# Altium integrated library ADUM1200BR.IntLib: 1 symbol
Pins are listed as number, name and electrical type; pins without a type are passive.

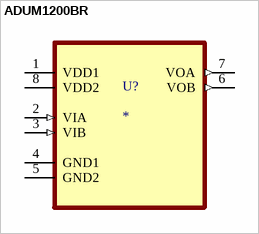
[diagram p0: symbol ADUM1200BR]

## ADUM1200BR
designator U?
General Purpose Digital Isolator 2500Vrms 2 Channel 10Mbps 25kV/Âµs CMTI 8-SOIC (0.154, 3.90mm Width); MF: Analog Devices; MP: ADUM1200BR
footprint SOIC127P600X175-8N
pins: 1 VDD1 (power), 2 VIA (in), 3 VIB (in), 4 GND1, 5 GND2, 6 VOB (out), 7 VOA (out), 8 VDD2 (power)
